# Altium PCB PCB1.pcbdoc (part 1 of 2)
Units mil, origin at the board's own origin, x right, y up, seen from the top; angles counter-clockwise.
Board outline 26305 x 7340 mil, 4 copper layers (Top Layer, Inner1, Inner2, Bottom Layer); 215 components, 225 nets, 1133 pads, 8 vias.
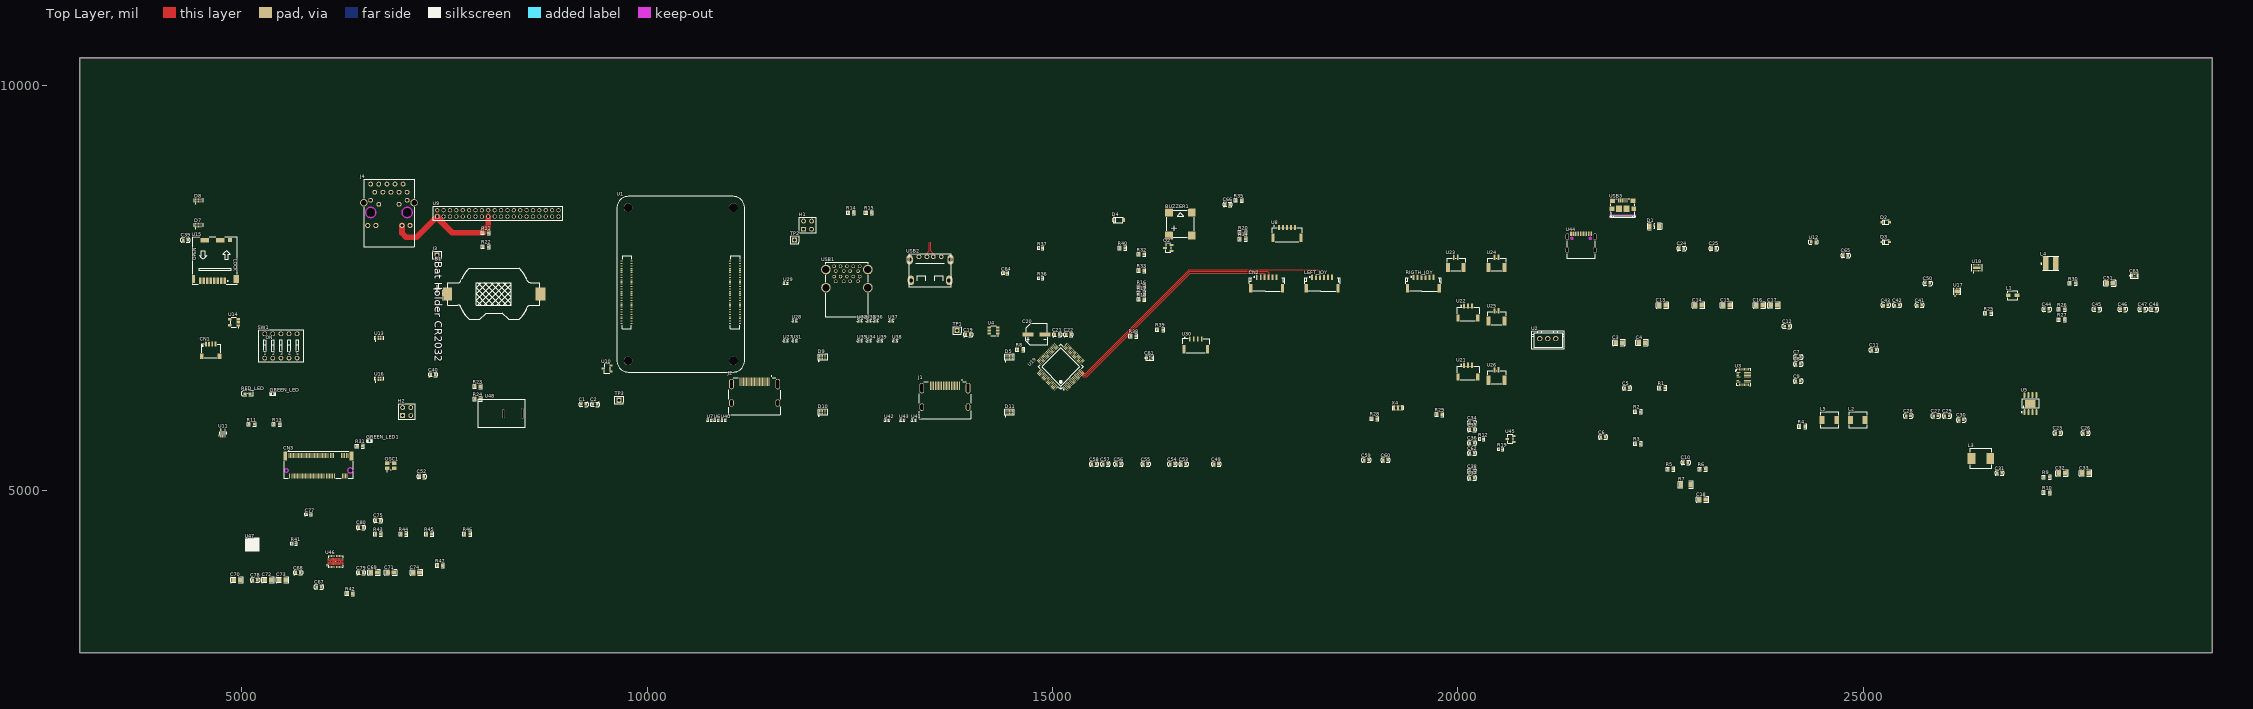
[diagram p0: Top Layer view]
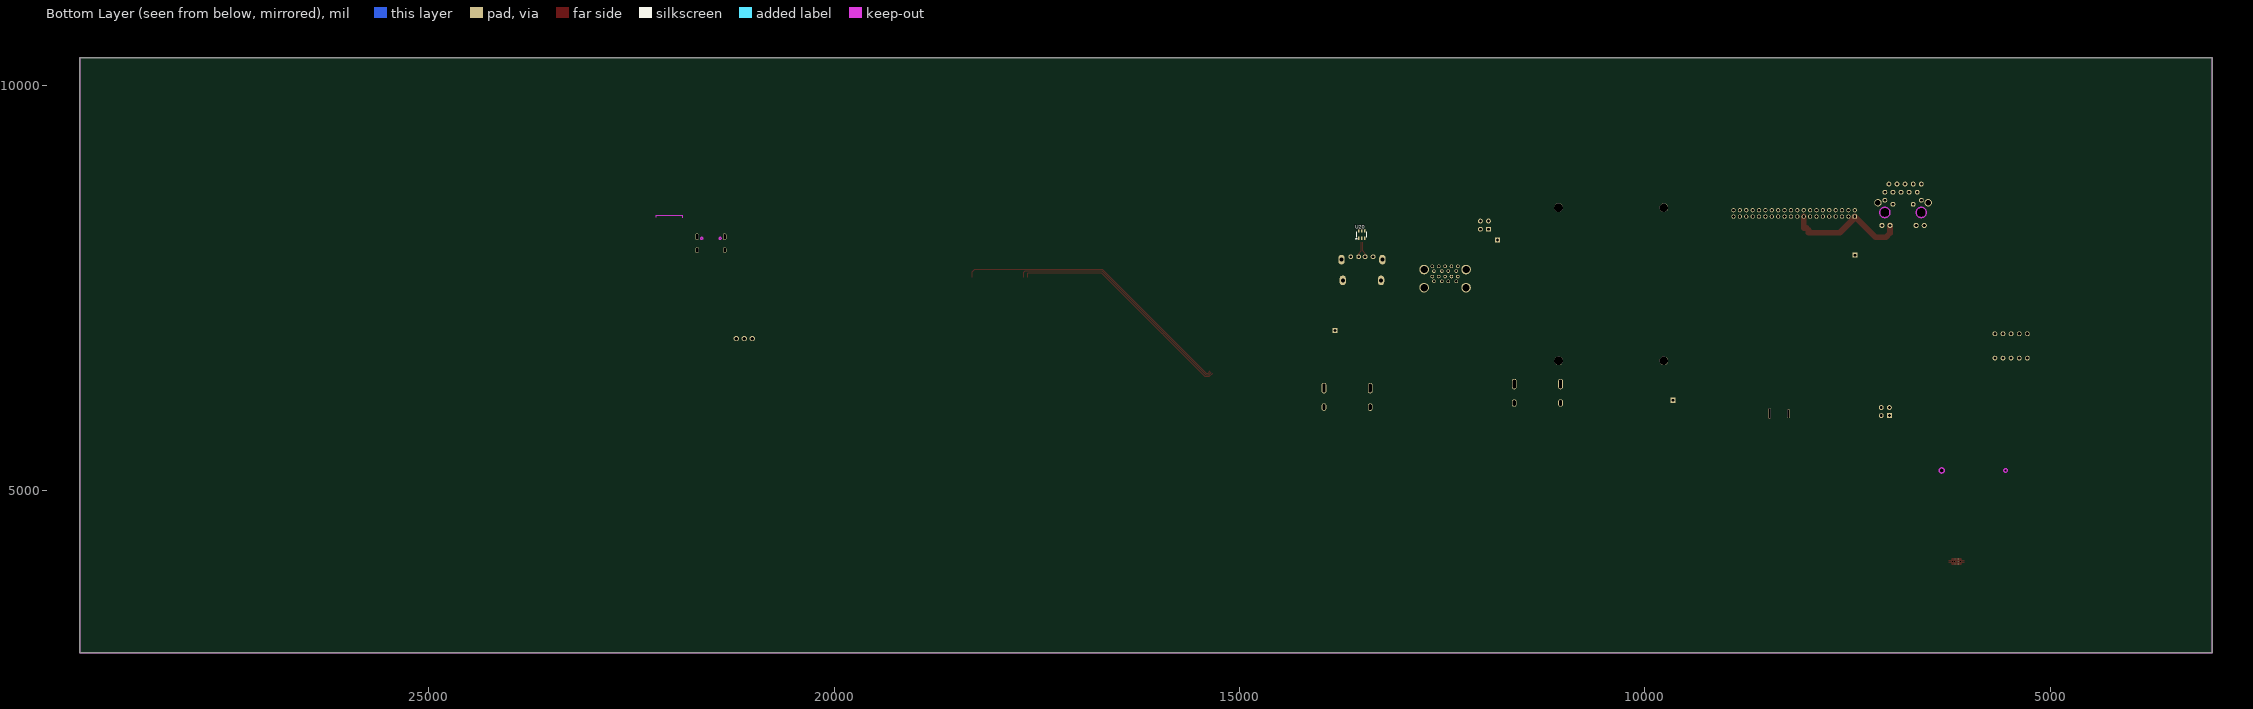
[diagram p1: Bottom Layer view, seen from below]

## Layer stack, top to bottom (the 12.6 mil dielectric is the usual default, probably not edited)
Top Layer: signal copper (thickness not stored)
Dielectric: dielectric 12.6, FR-4, Dk 4.8
Inner1: signal copper (thickness not stored)
Dielectric: dielectric 12.6, FR-4, Dk 4.8
Inner2: signal copper (thickness not stored)
Dielectric: dielectric 12.6, FR-4, Dk 4.8
Bottom Layer: signal copper (thickness not stored)

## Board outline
3000,10340 29305,10340 29305,3000 3000,3000

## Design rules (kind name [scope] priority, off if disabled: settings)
BoardOutlineClearance copperThickness1oz [All] p0: genericclearance=10 ignorepadtopadclearanceinfootprint=FALSE except(0: Arc-SplitContinuation Track-SplitContinuation SMDPad-SplitContinuation THPad-SplitContinuation Via-SplitContinuation Fill-SplitContinuation Poly-SplitContinuation Region-SplitContinuation Text-SplitContinuation; 6: Track-CutoutEdge SMDPad-CutoutEdge THPad-CutoutEdge Via-CutoutEdge Region-CutoutEdge; 11.8: Track-OutlineEdge SMDPad-OutlineEdge THPad-OutlineEdge Via-OutlineEdge Fill-OutlineEdge Region-OutlineEdge Poly-OutlineEdge Text-OutlineEdge Fill-CutoutEdge)
BoardOutlineClearance copperThickness2oz [All] p0: genericclearance=10 ignorepadtopadclearanceinfootprint=FALSE except(0: Arc-SplitContinuation Track-SplitContinuation SMDPad-SplitContinuation THPad-SplitContinuation Via-SplitContinuation Fill-SplitContinuation Poly-SplitContinuation Region-SplitContinuation Text-SplitContinuation; 6: Track-CutoutEdge SMDPad-CutoutEdge THPad-CutoutEdge Via-CutoutEdge Region-CutoutEdge; 11.8: Track-OutlineEdge SMDPad-OutlineEdge THPad-OutlineEdge Via-OutlineEdge Fill-OutlineEdge Region-OutlineEdge Poly-OutlineEdge Text-OutlineEdge Fill-CutoutEdge)
BoardOutlineClearance safeClearance1 [All] p0: genericclearance=10 ignorepadtopadclearanceinfootprint=FALSE except(0: Arc-SplitContinuation Track-SplitContinuation SMDPad-SplitContinuation THPad-SplitContinuation Via-SplitContinuation Fill-SplitContinuation Poly-SplitContinuation Region-SplitContinuation Text-SplitContinuation; 6: Track-CutoutEdge SMDPad-CutoutEdge THPad-CutoutEdge Via-CutoutEdge Fill-CutoutEdge Region-CutoutEdge; 11.8: Track-OutlineEdge SMDPad-OutlineEdge THPad-OutlineEdge Via-OutlineEdge Fill-OutlineEdge Region-OutlineEdge Poly-OutlineEdge Text-OutlineEdge)
Clearance copperThickness1oz [(InNet('AGND') OR InNet('VBAT') OR InNet('MCU_3V3') OR InNet('$4N108') OR InNet('CM_5V') OR InNet('HDMI_5V') OR InNet('$2N10') OR InNet('$2N12') OR InNet('BST1') OR InNet('SW1') OR InNet('BST2') OR InNet('SW2') OR InNet('BST3') OR InNet('SW3') OR InNet('$2N31') OR InNet('$2N30') OR InNet('IN') OR InNet('$2N37') OR InNet('SYS') OR InNet('VBUS') OR InNet('5V_USB3.0') OR InNet('$2N83') OR InNet('$2N84') OR InNet('$2N89') OR InNet('$2N91') OR InNet('+5V_RT') OR InNet('FB1') OR InNet('ADC1_IN0') OR InNet('ADC1_IN1') OR InNet('ADC1_IN2') OR InNet('ADC1_IN5') OR InNet('ADC1_IN4') OR InNet('SD_PWR') OR InNet('$3N153') OR InNet('M2_3V3') OR InNet('FB') OR InNet('$2N54') OR InNet('$2N58') OR InNet('$4N13') OR InNet('$4N14') OR InNet('SWD_5V') OR InNet('$4N18') OR InNet('ADC1_IN3') OR InNet('PWRB_STM32') OR InNet('TACHO') OR InNet('PWM') OR InNet('$3N203') OR InNet('PCIE_CLK_P') OR InNet('PCIE_NWAKE') OR InNet('PCIE_CLK_N') OR InNet('PCIE_NCLKREQ') OR InNet('PCIE_NRST') OR InNet('PCIE_TX_N') OR InNet('PCIE_TX_P') OR InNet('PCIE_RX_N') OR InNet('PCIE_RX_P') OR InNet('$3N198') OR InNet('$2N45') OR InNet('HDMI0_D2_P') OR InNet('HDMI0_D2_N') OR InNet('HDMI0_D1_P') OR InNet('HDMI0_D1_N') OR InNet('SD_DAT1') OR InNet('SD_DAT0') OR InNet('SD_CLK') OR InNet('SD_CMD') OR InNet('SD_DAT3') OR InNet('SD_DAT2') OR InNet('HDMI1_D2_P') OR InNet('HDMI1_D2_N') OR InNet('HDMI1_D1_P') OR InNet('HDMI1_D1_N') OR InNet('HDMI1_D0_P') OR InNet('HDMI1_D0_N') OR InNet('HDMI1_CK_P') OR InNet('HDMI1_CK_N') OR InNet('HDMI0_D0_P') OR InNet('HDMI0_D0_N') OR InNet('HDMI0_CK_P') OR InNet('HDMI0_CK_N') OR InNet('+3.3V') OR InNet('$3N118') OR InNet('$3N199') OR InNet('ID_SC') OR InNet('SCL1') OR InNet('ID_SD') OR InNet('SDA1') OR InNet('TR1_TAP') OR InNet('TR2_TAP') OR InNet('TR0_TAP') OR InNet('TR3_TAP') OR InNet('HDMI0_HOTPLUG') OR InNet('HDMI0_SDA') OR InNet('HDMI0_SCL') OR InNet('$1N18') OR InNet('HDMI0_CEC') OR InNet('HDMI1_HOTPLUG') OR InNet('HDMI1_SDA') OR InNet('HDMI1_SCL') OR InNet('$1N31') OR InNet('HDMI1_CEC') OR InNet('$3N62') OR InNet('$3N162') OR InNet('$3N161') OR InNet('TRD0_N') OR InNet('TRD2_N') OR InNet('TRD1_N') OR InNet('TRD3_N') OR InNet('TRD3_P') OR InNet('TRD2_P') OR InNet('TRD1_P') OR InNet('TRD0_P') OR InNet('$2N68') OR InNet('$2N57') OR InNet('$4N103') OR InNet('$2N9') OR InNet('NTC') OR InNet('$2N29') OR InNet('$1N121') OR InNet('$3N114') OR InNet('$3N115') OR InNet('$4N99') OR InNet('OFF/ON_CM5') OR InNet('LED_NACT') OR InNet('GPIO_VREF') OR InNet('ACOK') OR InNet('PROCHOT') OR InNet('INT') OR InNet('$4N114') OR InNet('LED_RED') OR InNet('+1.8V') OR InNet('ETH_LEDY') OR InNet('ETH_LEDG') OR InNet('PCIE_PWR_EN') OR InNet('$4N9') OR InNet('$4N11') OR InNet('$2N59') OR InNet('I2C1_SDA') OR InNet('I2C1_SCL') OR InNet('$4N115') OR InNet('LED_GREEN') OR InNet('$1N155') OR InNet('USB2_N') OR InNet('USB2_P') OR InNet('$1N156') OR InNet('SWDIO') OR InNet('SWCLK') OR InNet('TIM3_CH4') OR InNet('NRPIBOOT') OR InNet('EEPROM_NWP') OR InNet('USBOTG_ID') OR InNet('WIFI_NDISABLE') OR InNet('BT_NDISABLE') OR InNet('$3N7') OR InNet('GPIO26') OR InNet('CM5_GPIO_IN') OR InNet('GPIO19') OR InNet('GPIO20') OR InNet('GPIO13') OR InNet('GPIO16') OR InNet('GPIO6') OR InNet('GPIO12') OR InNet('GPIO5') OR InNet('GPIO7') OR InNet('GPIO11') OR InNet('GPIO8') OR InNet('GPIO9') OR InNet('GPIO25') OR InNet('GPIO10') OR InNet('GPIO24') OR InNet('GPIO22') OR InNet('GPIO23') OR InNet('GPIO27') OR InNet('GPIO18') OR InNet('GPIO17') OR InNet('GPIO15') OR InNet('GPIO4') OR InNet('GPIO14') OR InNet('GPIO3') OR InNet('GPIO2') OR InNet('$3N25') OR InNet('SD_PWR_ON') OR InNet('PWR_BUT') OR InNet('CC1') OR InNet('NPWR_LED') OR InNet('CC2') OR InNet('$1N122') OR InNet('VBUS_EN') OR InNet('USB3-0-RX_N') OR InNet('USB3-0-RX_P') OR InNet('USB3-0-D_P') OR InNet('USB3-0-D_N') OR InNet('$1N88') OR InNet('USB3-0-TX_N') OR InNet('$1N87') OR InNet('USB3-0-TX_P') OR InNet('USB3-1-RX_N') OR InNet('USB3-1-RX_P') OR InNet('USB3-1-D_P') OR InNet('USB3-1-D_N') OR InNet('USB3-1-TX_N') OR InNet('USB3-1-TX_P') OR InNet('EN_5V') OR InNet('GPIO_IN1') OR InNet('GPIO_IN0') OR InNet('GPIO_IN7') OR InNet('GPIO_IN6') OR InNet('GPIO_IN5') OR InNet('GPIO_IN4') OR InNet('GPIO_IN3') OR InNet('GPIO_IN2') OR InNet('$4N8') OR InNet('$4N7') OR InNet('D+') OR InNet('D-') OR InNet('$2N3270') OR InNet('$2N3397') OR InNet('$2N3401') OR InNet('$2N4875') OR InNet('$2N4576') OR InNet('$2N4443') OR InNet('$2N4479') OR InNet('$2N3574') OR InNet('$2N3583') OR InNet('$2N4890'))] p1: gap=7 ignorepadtopadclearanceinfootprint=FALSE except(4: Track-Track; 6: Track-SMDPad SMDPad-SMDPad Track-THPad SMDPad-THPad THPad-THPad Track-Via SMDPad-Via THPad-Via Via-Via SMDPad-Fill THPad-Fill Via-Fill Fill-Fill Track-Region SMDPad-Region THPad-Region Via-Region Region-Region Track-Poly SMDPad-Poly THPad-Poly Via-Poly Fill-Poly Region-Poly Poly-Poly Track-Text SMDPad-Text THPad-Text Via-Text Fill-Text Region-Text Poly-Text Text-Text; 6.9: Track-Hole SMDPad-Hole THPad-Hole Via-Hole Fill-Hole Region-Hole Poly-Hole Text-Hole Sheet-Hole; 11.8: Track-Fill Fill-Region Track-Sheet SMDPad-Sheet THPad-Sheet Via-Sheet Fill-Sheet Region-Sheet Poly-Sheet Text-Sheet)
Clearance copperThickness2oz [All] p1: gap=7 ignorepadtopadclearanceinfootprint=FALSE except(6: Track-SMDPad SMDPad-SMDPad Track-THPad SMDPad-THPad THPad-THPad Track-Via SMDPad-Via THPad-Via Via-Via SMDPad-Fill THPad-Fill Via-Fill Fill-Fill Track-Region SMDPad-Region THPad-Region Via-Region Region-Region Track-Poly SMDPad-Poly THPad-Poly Via-Poly Fill-Poly Region-Poly Poly-Poly Track-Text SMDPad-Text THPad-Text Via-Text Fill-Text Region-Text Poly-Text Text-Text; 6.9: Track-Hole SMDPad-Hole THPad-Hole Via-Hole Fill-Hole Region-Hole Poly-Hole Text-Hole Sheet-Hole; 8: Track-Track; 11.8: Track-Fill Fill-Region Track-Sheet SMDPad-Sheet THPad-Sheet Via-Sheet Fill-Sheet Region-Sheet Poly-Sheet Text-Sheet)
Clearance safeClearance1 [All] p1: gap=7 ignorepadtopadclearanceinfootprint=FALSE except(6: Track-Track Track-SMDPad SMDPad-SMDPad Track-THPad SMDPad-THPad THPad-THPad Track-Via SMDPad-Via THPad-Via Via-Via Track-Fill SMDPad-Fill THPad-Fill Via-Fill Fill-Fill Track-Region SMDPad-Region THPad-Region Via-Region Fill-Region Region-Region Track-Poly SMDPad-Poly THPad-Poly Via-Poly Fill-Poly Region-Poly Poly-Poly Track-Text SMDPad-Text THPad-Text Via-Text Fill-Text Region-Text Poly-Text Text-Text Track-Hole SMDPad-Hole THPad-Hole Via-Hole Fill-Hole Region-Hole Poly-Hole Text-Hole; 11.8: Track-Sheet SMDPad-Sheet THPad-Sheet Via-Sheet Fill-Sheet Region-Sheet Poly-Sheet Text-Sheet Sheet-Hole)
DiffPairsRouting differentialPair [All] p1: maxuncoupledlength=10 minlimit=6 maxlimit=6 mostfreqgap=6 toplayer_minwidth=5 toplayer_prefwidth=10 toplayer_maxwidth=100 bottomlayer_minwidth=5 bottomlayer_prefwidth=10 bottomlayer_maxwidth=100 midlayer1_minwidth=5 midlayer1_prefwidth=10 midlayer1_maxwidth=100 midlayer2_minwidth=5 midlayer2_prefwidth=10 midlayer2_maxwidth=100
PasteMaskExpansion pasteMaskExpansion [All] p1: expansion=0
PlaneConnect innerPlane [All] p1: planeconnectstyle=Relief reliefexpansion=20 reliefentries=4 reliefconductorwidth=10 reliefairgap=10
PolygonConnect copperRegion [All] p1: connectstyle=Relief reliefentries=4 reliefconductorwidth=10 polygonreliefangle="90 Angle" airgapwidth=10
RoutingVias viaSize [All] p1: viastyle="Through Hole" holewidth=12.0078 minholewidth=11.811 maxholewidth=248.0314 width=24.0158 minwidth=19.685 maxwidth=393.7008
SolderMaskExpansion solderMaskExpansion [All] p1: useseparateexpansions=TRUE expansion=2 expansionbottom=2
Width copperThickness1oz [All] p1: maxlimit=100 minlimit=5 preferedwidth=10
Width copperThickness2oz [All] p1: maxlimit=100 minlimit=8 preferedwidth=10
Width Power [All] p1: maxlimit=197 minlimit=59 preferedwidth=71

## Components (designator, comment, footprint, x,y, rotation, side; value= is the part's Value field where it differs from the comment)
B1 "KLS5-CR1220-01" L-KLS5-CR2032-23-B1 8108.44,7425.03 r0 top
BUZZER1 "2700Hz" BUZ-SMD_4P-L8.5-W8.5-P8.50-BR 16576.98,8287.53 r0 top
C1 "100nF" C0603 9216.73,6064.16 r0 top
C2 "100nF" C0603 9355.86,6064.16 r0 top
C3 "22uF" C0805 21984.28,6824.69 r0 top
C4 "22uF" C0805 22271.22,6824.69 r0 top
C5 "100nF" C0603 22084.28,6263.8 r0 top
C6 "1uF" C0603 21788.46,5659.49 r0 top
C7 "470nF" C0603 24196.57,6647.87 r0 top
C8 "470nF" C0603 24196.57,6562.28 r0 top
C9 "470nF" C0603 24196.57,6349.4 r0 top
C10 "100nF" C0603 22808.16,5346.2 r0 top
C11 "1uF" C0603 25130.65,6733.47 r0 top
C12 "10uF" C0603 24057.44,7026.81 r0 top
C13 "22uF" C0805 22521.22,7286.16 r0 top
C14 "22uF" C0805 22967.88,7286.16 r0 top
C15 "22uF" C0805 23314.53,7286.16 r0 top
C16 "22uF" C0805 23717.43,7286.16 r0 top
C17 "22uF" C0805 23897.73,7286.16 r0 top
C18 "22uF" C0805 23017.88,4888.93 r0 top
C19 "10uF" C0603 13958.15,6923.07 r0 top
C20 "100uF" CAP-SMD_BD6.3-L6.6-W6.6-LS7.6-FD 14802.8,6923.07 r0 top
C21 "10uF" C0603 15056.22,6923.07 r0 top
C22 "10uF" C0603 15195.35,6923.07 r0 top
C23 "3.3nF" C0603 27398.31,5709.49 r0 top
C24 "100nF" C0603 22758.16,7985.11 r0 top
C25 "100nF" C0603 23154.81,7985.11 r0 top
C26 "1uF" C0603 27740.58,5709.49 r0 top
C27 "10uF" C0603 25893.31,5922.79 r0 top
C28 "10uF" C0603 25554.18,5922.79 r0 top
C29 "100nF" C0603 26032.44,5922.79 r0 top
C30 "100nF" C0603 26207.22,5872.79 r0 top
C31 "5pF" C0603 26678.62,5214.55 r0 top
C32 "22uF" C0805 27448.31,5214.55 r0 top
C33 "22uF" C0805 27740.58,5214.55 r0 top
C34 "100nF" C0603 20173.12,5837.26 r0 top
C35 "100nF" C0603 20173.12,5751.66 r0 top
C36 "100nF" C0603 20173.12,5586.52 r0 top
C37 "100nF" C0603 20173.12,5154.47 r0 top
C38 "100nF" C0603 20173.12,5240.06 r0 top
C39 "10uF" C0603 4304.72,8090.01 r0 top
C40 "0.1u" C0603 7358.44,6430.65 r0 top
C41 "100nF" C0603 25693.31,7286.16 r0 top
C42 "10uF" C0603 25415.05,7286.16 r0 top
C43 "10uF" C0603 25275.91,7286.16 r0 top
C44 "4.7nF" C0603 27261.37,7236.16 r0 top
C45 "10uF" C0603 27879.71,7236.16 r0 top
C46 "10uF" C0603 28199.14,7236.16 r0 top
C47 "10uF" C0603 28444.49,7236.16 r0 top
C48 "10uF" C0603 28583.62,7236.16 r0 top
C49 "1uF" C0603 17019.02,5325.66 r0 top
C50 "2.2uF" C0603 25793.31,7556.38 r0 top
C51 "22uF" C0805 28039.43,7556.38 r0 top
C52 "100nF" C0603 7219.31,5174.46 r0 top
C53 "100nF" C0603 16616.11,5325.66 r0 top
C54 "100nF" C0603 16476.98,5325.66 r0 top
C55 "100nF" C0603 16147.22,5325.66 r0 top
C56 "100nF" C0603 15812.47,5325.66 r0 top
C57 "100nF" C0603 15650.78,5325.66 r0 top
C58 "100nF" C0603 15511.64,5325.66 r0 top
C59 "2.2uF" C0603 18869.94,5375.66 r0 top
C60 "2.2uF" C0603 19106.88,5375.66 r0 top
C61 "-" FILTER-SMD_3P-L1.6-W0.8-L_NFM18CC223R1C3D 16197.22,6635.93 r0 top
C62 "100nF" C0603 20173.12,5461.26 r0 top
C63 "-" FILTER-SMD_3P-L1.6-W0.8-L_NFM18CC223R1C3D 28344.49,7649.51 r0 top
C64 "100nF" C0402 14416.65,7683.96 r0 top
C65 "47uF" C0603 24781.17,7899.51 r0 top
C66 "100nF" C0603 17158.15,8529.14 r0 top
C67 "06035C473KAT2A" C0603 5951.14,3811.55 r0 top
C68 "CC0603KRX7R9BB104" C0603 5694.3,3988.36 r0 top
C69 "GRM219R61C226ME15L" C0805 6630.13,3988.36 r0 top
C70 "GRM219R61C226ME15L" C0805 4939.12,3897.15 r0 top
C71 "GRM219R61C226ME15L" C0805 6837.65,3988.36 r0 top
C72 "GRM219R61C226ME15L" C0805 5323.83,3897.15 r0 top
C73 "GRM219R61C226ME15L" C0805 5504.13,3897.15 r0 top
C74 "GRM219R61C226ME15L" C0805 7152.7,3988.36 r0 top
C75 "CC0603KRX7R9BB102" C0603 6680.13,4631.33 r0 top
C77 "GRM155R61C225KE11D" C0402 5822.72,4706.6 r0 top
C78 "CC0603KRX7R9BB104" C0603 5164.12,3897.15 r0 top
C79 "CC0603KRX7R9BB104" C0603 6470.41,3988.36 r0 top
C80 "CAP_0603" C0603 6470.41,4545.73 r0 top
CN1 "SM04B-SRSS-TB (LF)(SN)" CONN-SMD_4P-P1.00_SM04B-SRSS-TB-LF-SN 4616.59,6733.4 r0 top
CN2 "STICK LEFT" CONN-TH_SM06B-GHS-TB-LF-SN 17641.21,7563.61 r0 top
CN3 "MDT275M02001-CUST" PCI-SMD_APCI0164-P001A 5944.79,5307.1 r0 top
D1 "MF-NSML600/6-2" F1206 22421.22,8261.12 r0 top
D2 "BAT60AE6327HTSA1" SOD-323_L1.8-W1.3-LS2.5-RD 25275.91,8311.12 r0 top
D3 "BAT60AE6327HTSA1" SOD-323_L1.8-W1.3-LS2.5-RD 25275.91,8066.39 r0 top
D4 "BAS16W" SOD-123_L2.7-W1.6-LS3.7-RD 15812.47,8337.53 r0 top
D5 "ESD73034D" DFN-10_L2.5-W1.0-P0.50-BL-2 14466.65,6645.85 r0 top
D7 "TPD4E02B04DQAR" USON-10_L2.5-W1.0-P0.50-BL 4466.59,8275.39 r0 top
D8 "TPD4E02B04DQAR" USON-10_L2.5-W1.0-P0.50-BL 4466.59,8579.84 r0 top
D9 "ESD73034D" DFN-10_L2.5-W1.0-P0.50-BL-2 12163.41,6645.85 r0 top
D10 "ESD73034D" DFN-10_L2.5-W1.0-P0.50-BL-2 12163.41,5967.59 r0 top
D11 "ESD73034D" DFN-10_L2.5-W1.0-P0.50-BL-2 14466.65,5967.59 r0 top
GREEN_LED "TO-1608BC" 1608 5382.57,6196.27 r0 top
GREEN_LED1 "TO-1608BC" 1608 6574.72,5614.73 r0 top
H1 "HDR-F-2.54_2x2" HDR-F-2.54_2X2 11978.78,8273.54 r0 top
H2 "HDR-F-2.54_2x2" HDR-F-2.54_2X2 7033.9,5973.82 r0 top
J1 "CM4IO_HDMI_A_1.4" "EDAC 690-019-298-412" 13672.29,6264.16 r0 top
J2 "CM4IO_HDMI_A_1.4" "EDAC 690-019-298-412" 11325.09,6314.16 r0 top
J3 "3.3V_eMMC" HDR-M-2.54_1X1 7408.44,7903.21 r0 top
J4 "LPJG0926HENL" RJ45-TH_LPJG0926HENL_C22457393 6815,8525 r0 top
L1 "2.2uH" IND-SMD_L3.0-W3.0_IHLP-1212BZ 26840.7,7408.48 r0 top
L2 "1.5uH" IND-SMD_L5.5-W5.2 24931.17,5872.79 r0 top
L3 "3.3uH" IND-SMD_L6.5-W6.5_IHLP-2525 26449.41,5396.2 r0 top
L4 "10uH" IND-SMD_L4.0-W4.0_VLCF4020 27311.37,7799.51 r0 top
L5 "1.5uH" IND-SMD_L5.5-W5.2 24581.69,5872.79 r0 top
LEFT_JOY "STICK RIGHT" CONN-TH_SM06B-GHS-TB-LF-SN 18324.8,7563.61 r0 top
OSC1 "32.768kHz" OSC-SMD_4P-L3.2-W2.5-BL-1 6835.89,5307.1 r0 top
Q2 "SS8050" SOT-23-3_L2.9-W1.3-P1.90-LS2.4-BR 16426.98,7992.34 r0 top
R1 "100Ω" R0603 22521.22,6263.8 r0 top
R2 "13.7kΩ" R0603 22221.22,5972.79 r0 top
R3 "37.4kΩ" R0603 22221.22,5577.84 r0 top
R4 "10k" R0603 24246.57,5791.14 r0 top
R5 "2Ω" R0603 22621.22,5264.55 r0 top
R6 "2Ω" R0603 23017.88,5264.55 r0 top
R7 "10mΩ" R1206 22808.16,5070.37 r0 top
R8 "15kΩ" R0603 14602.8,6738.48 r0 top
R9 "124k" R0603 27261.37,5164.55 r0 top
R10 "22.1k" R0603 27261.37,4976.2 r0 top
R11 "1k" R0603 5121.66,5817.67 r0 top
R12 "100Ω" R0402 20292.71,5636.52 r0 top
R13 "1k" R0603 5432.57,5817.67 r0 top
R14 "2.2k 1%" R0603 12513.41,8428.23 r0 top
R15 "2.2k 1%" R0603 12734.83,8428.23 r0 top
R16 "10k" R0603 16097.22,7513.61 r0 top
R17 "10k" R0603 16097.22,7435.91 r0 top
R18 "10k" R0603 16097.22,7358.21 r0 top
R19 "100kOm" R0402 20525.6,5511.26 r0 top
R20 "300" R0603 17345.09,8181.82 r0 top
R21 "0" R0603 8008.44,8178.7 r0 top
R22 "0" R0603 8008.44,8008.36 r0 top
R23 "470" R0603 7908.44,6283.96 r0 top
R24 "470" R0603 7908.44,6128.51 r0 top
R25 "100k" R0603 26541.68,7186.16 r0 top
R26 "10k" R0603 27448.31,7236.16 r0 top
R27 "2.2k" R0603 27448.31,7108.46 r0 top
R28 "10k" R0603 18969.94,5887.26 r0 top
R29 "10k" R0603 19772.88,5937.26 r0 top
R30 "100k" R0603 27583.05,7556.38 r0 top
R31 "1k" R0603 6457.01,5546.98 r0 top
R32 "10k" R0603 16097.22,7914.64 r0 top
R33 "10k" R0603 16097.22,7714.64 r0 top
R34 "300" R0603 17345.09,8104.12 r0 top
R35 "10k" R0603 17295.09,8579.14 r0 top
R36 "22Ω" R0402 14852.8,7619.01 r0 top
R37 "22Ω" R0402 14852.8,7992.62 r0 top
R38 "10k" R0603 15997.22,6906.58 r0 top
R39 "10k" R0603 16326.98,6984.28 r0 top
R40 "1k" R0603 15862.47,7992.34 r0 top
R41 "RC0402FR-07590KL" R0402 5644.3,4346.29 r0 top
R42 "RC0603FR-07100KL" R0603 6333.47,3729.91 r0 top
R43 "Res_0603" R0603 6680.13,4464.09 r0 top
R44 "RC0603FR-07100KL" R0603 6995.17,4464.09 r0 top
R45 "RC0603FR-0795K3L" R0603 7310.22,4464.09 r0 top
R46 "RC0603FR-07127KL" R0603 7781.24,4464.09 r0 top
R47 "RC0603FR-07316KL" R0603 7444.97,4075.63 r0 top
RED_LED "TO-1608BC" SENSOR-SMD_L1.6-W0.8-XL-1608PDC 5071.66,6196.27 r0 top
RIGTH_JOY "STICK CAMERA GIMBAL" CONN-TH_SM06B-GHS-TB-LF-SN 19572.88,7563.61 r0 top
SW1 "DS1040-05RT" SW-TH_10P-P2.54_DS1040-05RN 5482.57,6783.4 r0 top
TP1 "HDR-M-2.54_1x1" HDR-M-2.54_1X1 13822.29,6973.07 r0 top
TP2 "HDR-M-2.54_1x1" HDR-M-2.54_1X1 11818.14,8089.93 r0 top
TP3 "HDR-M-2.54_1x1" HDR-M-2.54_1X1 9652.52,6114.16 r0 top
U1 "Raspberry Pi CM5" CM5IO:Raspberry-Pi-5-Compute-Module 9765,6600 r0 top
U2 "BAT 2s" CONN-TH_XH2.54-3P 21107.78,6874.69 r0 top
U3 "MP2762AGV-0000-Z" QFN-30_L5.0-W4.0-P0.50-TL_MP2762A 23517.04,6399.4 r0 top
U4 "AP22653W6-7" SOT-23-6_L2.9-W1.6-P0.95-LS2.8-BR 14273.15,6973.07 r0 top
U5 "RT6206BHGSP" SOP-8_L4.9-W3.9-P1.27-LS6.0-BL-EP-2 27060.09,6072.79 r0 top
U6 "ESD5311N" DFN1006-2L-BI 10855.5,5871.1 r0 top
U7 "ESD5311N" DFN1006-2L-BI 10768.83,5871.1 r0 top
U8 "Power_button" CONN-SMD_5P-P1.25_SM05B-GHS-TB-LF-SN 17891.21,8181.82 r0 top
U9 "DS1023-2X20" HDR-TH_40P-P2.00-V-F-R2-C20-S2.00 8158.44,8418.64 r0 top
U10 "RT9742SNGV_C3235509" SOT-23-3_L2.9-W1.6-P1.90-LS2.8-BR 9504.96,6503.63 r0 top
U11 "74LVC1G07SE-7" SC-88A_L2.0-W1.3-P0.65-LS2.1-BL 4766.59,5711.22 r0 top
U12 "BLM18PG121SH1D" L0603 24382.86,8066.39 r0 top
U13 "TPD4EUSB30DQAR" USON-10_L2.5-W1.0-P0.50-BL 6690.12,6883.4 r0 top
U14 "RT9742GGJ5" TSOT-23-5_L2.9-W1.6-P0.95-LS2.8-BR 4902.87,7075.03 r0 top
U15 "SD CARD SOCKET DM3C-SF HIROSE" TF-SMD_DM3CS-SF 4666.59,7840.01 r0 top
U16 "TPD4EUSB30DQAR" USON-10_L2.5-W1.0-P0.50-BL 6690.12,6380.65 r0 top
U17 "AP3441SHE-7B" DFN2020-8_L2.0-W2.0-P0.50-BL-EP 26157.22,7458.48 r0 top
U18 "TPS62177DQCR" WSON-10_L3.0-W2.0-P0.50-BL-EP 26399.41,7749.51 r0 top
U19 "STM32F405RGT6" LQFP-64_L10.0-W10.0-P0.50-LS12.0-BL 15100.43,6525.23 r45 top
U20 "USBLC6-2SC6_C6807798" SOT-23-6_L2.9-W1.6-P0.95-LS2.8-BL 13491.61,8156.83 r180 bottom
U21 "3 pos" CONN-TH_SM03B-GHS-TB-LF-SN 20123.12,6474.92 r0 top
U22 "3 pos" CONN-TH_SM03B-GHS-TB-LF-SN 20123.12,7203.05 r0 top
U23 "2 pos" CONN-SMD_SM02B-GHS-TB-LF-SN 19973.12,7814.64 r0 top
U24 "2 pos" CONN-SMD_SM02B-GHS-TB-LF-SN 20475.6,7814.64 r0 top
U25 "2 pos" CONN-SMD_SM02B-GHS-TB-LF-SN 20475.6,7153.05 r0 top
U26 "2 pos" CONN-SMD_SM02B-GHS-TB-LF-SN 20475.6,6424.92 r0 top
U27 "ESD5311N" DFN1006-2L-BI 11709.96,6852.69 r0 top
U28 "ESD5311N" DFN1006-2L-BI 11818.14,7096.43 r0 top
U29 "ESD5311N" DFN1006-2L-BI 11709.96,7558.95 r0 top
U30 "SM04B-GHS-TB(LF)(SN)" CONN-SMD_4P-P1.25_SM04B-GHS-TB-LF-SN 16766.11,6806.58 r0 top
U31 "ESD5311N" DFN1006-2L-BI 11818.14,6852.69 r0 top
U32 "ESD5311N" DFN1006-2L-BI 12624.12,7096.43 r0 top
U33 "ESD5311N" DFN1006-2L-BI 12734.83,7096.43 r0 top
U34 "ESD5311N" DFN1006-2L-BI 12734.83,6852.69 r0 top
U35 "ESD5311N" DFN1006-2L-BI 12624.12,6852.69 r0 top
U36 "ESD5311N" DFN1006-2L-BI 12821.51,7096.43 r0 top
U37 "ESD5311N" DFN1006-2L-BI 13008.18,7096.43 r0 top
U38 "ESD5311N" DFN1006-2L-BI 13058.18,6852.69 r0 top
U39 "ESD5311N" DFN1006-2L-BI 12871.51,6852.69 r0 top
U40 "ESD5311N" DFN1006-2L-BI 10942.18,5871.1 r0 top
U41 "ESD5311N" DFN1006-2L-BI 13289.38,5871.1 r0 top
U42 "ESD5311N" DFN1006-2L-BI 12958.18,5871.1 r0 top
U43 "ESD5311N" DFN1006-2L-BI 13144.86,5871.1 r0 top
U44 "TYPE-C" USB-C-SMD_TYPE-C16PIN-SHOUHAN 21519.18,8066.39 r0 top
U45 "BSS138" SOT-23-3_L2.9-W1.4-P1.90-LS2.5-BR 20647.27,5636.52 r0 top
U46 "TPS61088RHLR" VQFN-20_L4.6-W3.6-P0.50-BL 6156.46,4125.63 r0 top
U47 "CDCSAB0420-1R5M" CDCSAB0420-1R5M 5664.12,4046.29 r0 top
U48 "DS-201" DS-201 7919.61,6126.85 r0 top
USB1 "HC-USB3.0-L175-2X1-P" USB-A-TH_H181-AF2R06-12ALCR 12463.41,7633.96 r0 top
USB2 "USB-A DS1095-06-BNR0" DS1095-06-BNR0 13489.38,7883.96 r0 top
USB3 "1981568-1" MICRO-USB-SMD_1981568-1 22034.28,8528.92 r0 top
X4 "8MHz" OSC-SMD_3P-L3.2-W1.3-P1.2-L 19260.29,6019.42 r0 top

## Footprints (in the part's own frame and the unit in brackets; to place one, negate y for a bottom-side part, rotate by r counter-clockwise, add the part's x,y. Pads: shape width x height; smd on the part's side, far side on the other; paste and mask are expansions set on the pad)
1608 [mil]
  rect 26x38 smd: 1(-27.5,0) 2(27.5,0)
  silkscreen extent -34,-19 34,19
BUZ-SMD_4P-L8.5-W8.5-P8.50-BR [mil]
  rect 94.49x94.49 smd: 1(-141.72,-141.73) 2(141.72,-141.73) 3(141.72,141.72) 4(-141.72,141.73)
  silkscreen extent -167,-167 167,167
C0402 [mm]
  rect 0.79x0.54 smd: 1(-0.545,0) 2(0.545,0)
  silkscreen extent -1.17,-0.5 1.17,0.5
C0603 [mm]
  rect 0.8x0.9 smd: 1(-0.7,0) 2(0.7,0)
  silkscreen extent -1.39,-0.71 1.39,0.71
C0805 [mm]
  rect 1.41x1.35 smd: 1(-1,0) 2(1,0)
  silkscreen extent -1.96,-0.9 1.96,0.9
CAP-SMD_BD6.3-L6.6-W6.6-LS7.6-FD [mm]
  rect 3.5x1.2 smd: 1(-2.67,0) 2(2.67,0)
  silkscreen extent -3.38,-3.38 3.38,3.38
CDCSAB0420-1R5M [mm]
  rect 0.8x2 smd: 1(-15.475,7.255) 2(-11.811,7.239)
  silkscreen extent -15.85,5.17 -11.45,9.37
CM5IO:Raspberry-Pi-5-Compute-Module [mm]
  rect 0.7x0.2 smd: 1(-2.04,31.3) 2(1.04,31.3) 3(-2.04,30.9) 4(1.04,30.9) 5(-2.04,30.5) 6(1.04,30.5) 7(-2.04,30.1) 8(1.04,30.1) 9(-2.04,29.7) 10(1.04,29.7) 11(-2.04,29.3) 12(1.04,29.3) 13(-2.04,28.9) 14(1.04,28.9) 15(-2.04,28.5) 16(1.04,28.5) 17(-2.04,28.1) 18(1.04,28.1) 19(-2.04,27.7) 20(1.04,27.7) 21(-2.04,27.3) 22(1.04,27.3) 23(-2.04,26.9) 24(1.04,26.9) 25(-2.04,26.5) 26(1.04,26.5) 27(-2.04,26.1) 28(1.04,26.1) 29(-2.04,25.7) 30(1.04,25.7) 31(-2.04,25.3) 32(1.04,25.3) 33(-2.04,24.9) 34(1.04,24.9) 35(-2.04,24.5) 36(1.04,24.5) 37(-2.04,24.1) 38(1.04,24.1) 39(-2.04,23.7) 40(1.04,23.7) 41(-2.04,23.3) 42(1.04,23.3) 43(-2.04,22.9) 44(1.04,22.9) 45(-2.04,22.5) 46(1.04,22.5) 47(-2.04,22.1) 48(1.04,22.1) 49(-2.04,21.7) 50(1.04,21.7) 51(-2.04,21.3) 52(1.04,21.3) 53(-2.04,20.9) 54(1.04,20.9) 55(-2.04,20.5) 56(1.04,20.5) 57(-2.04,20.1) 58(1.04,20.1) 59(-2.04,19.7) 60(1.04,19.7) 61(-2.04,19.3) 62(1.04,19.3) 63(-2.04,18.9) 64(1.04,18.9) 65(-2.04,18.5) 66(1.04,18.5) 67(-2.04,18.1) 68(1.04,18.1) 69(-2.04,17.7) 70(1.04,17.7) 71(-2.04,17.3) 72(1.04,17.3) 73(-2.04,16.9) 74(1.04,16.9) 75(-2.04,16.5) 76(1.04,16.5) 77(-2.04,16.1) 78(1.04,16.1) 79(-2.04,15.7) 80(1.04,15.7) 81(-2.04,15.3) 82(1.04,15.3) 83(-2.04,14.9) 84(1.04,14.9) 85(-2.04,14.5) 86(1.04,14.5) 87(-2.04,14.1) 88(1.04,14.1) 89(-2.04,13.7) 90(1.04,13.7) 91(-2.04,13.3) 92(1.04,13.3) 93(-2.04,12.9) 94(1.04,12.9) 95(-2.04,12.5) 96(1.04,12.5) 97(-2.04,12.1) 98(1.04,12.1) 99(-2.04,11.7) 100(1.04,11.7) 101(31.96,31.3) 102(35.04,31.3) 103(31.96,30.9) 104(35.04,30.9) 105(31.96,30.5) 106(35.04,30.5) 107(31.96,30.1) 108(35.04,30.1) 109(31.96,29.7) 110(35.04,29.7) 111(31.96,29.3) 112(35.04,29.3) 113(31.96,28.9) 114(35.04,28.9) 115(31.96,28.5) 116(35.04,28.5) 117(31.96,28.1) 118(35.04,28.1) 119(31.96,27.7) 120(35.04,27.7) 121(31.96,27.3) 122(35.04,27.3) 123(31.96,26.9) 124(35.04,26.9) 125(31.96,26.5) 126(35.04,26.5) 127(31.96,26.1) 128(35.04,26.1) 129(31.96,25.7) 130(35.04,25.7) 131(31.96,25.3) 132(35.04,25.3) 133(31.96,24.9) 134(35.04,24.9) 135(31.96,24.5) 136(35.04,24.5) 137(31.96,24.1) 138(35.04,24.1) 139(31.96,23.7) 140(35.04,23.7) 141(31.96,23.3) 142(35.04,23.3) 143(31.96,22.9) 144(35.04,22.9) 145(31.96,22.5) 146(35.04,22.5) 147(31.96,22.1) 148(35.04,22.1) 149(31.96,21.7) 150(35.04,21.7) 151(31.96,21.3) 152(35.04,21.3) 153(31.96,20.9) 154(35.04,20.9) 155(31.96,20.5) 156(35.04,20.5) 157(31.96,20.1) 158(35.04,20.1) 159(31.96,19.7) 160(35.04,19.7) 161(31.96,19.3) 162(35.04,19.3) 163(31.96,18.9) 164(35.04,18.9) 165(31.96,18.5) 166(35.04,18.5) 167(31.96,18.1) 168(35.04,18.1) 169(31.96,17.7) 170(35.04,17.7) 171(31.96,17.3) 172(35.04,17.3) 173(31.96,16.9) 174(35.04,16.9) 175(31.96,16.5) 176(35.04,16.5) 177(31.96,16.1) 178(35.04,16.1) 179(31.96,15.7) 180(35.04,15.7) 181(31.96,15.3) 182(35.04,15.3) 183(31.96,14.9) 184(35.04,14.9) 185(31.96,14.5) 186(35.04,14.5) 187(31.96,14.1) 188(35.04,14.1) 189(31.96,13.7) 190(35.04,13.7) 191(31.96,13.3) 192(35.04,13.3) 193(31.96,12.9) 194(35.04,12.9) 195(31.96,12.5) 196(35.04,12.5) 197(31.96,12.1) 198(35.04,12.1) 199(31.96,11.7) 200(35.04,11.7)
  round 2.7 hole 2.7 unplated: ""(0,0) ""(0,48) ""(33,0) ""(33,48)
  silkscreen extent -3.5,-3.5 36.5,51.5
CONN-SMD_4P-P1.00_SM04B-SRSS-TB-LF-SN [mm]
  rect 0.6x1.55 smd: 1(-1.5,1.938) 2(-0.5,1.938) 3(0.5,1.938) 4(1.5,1.938)
  rect 1.2x1.8 smd: 5(2.8,-1.938) 6(-2.8,-1.938)
  silkscreen extent -3.02,-2.46 2.96,1.8
CONN-SMD_4P-P1.25_SM04B-GHS-TB-LF-SN [mm]
  rect 0.6x1.7 smd: 1(-1.876,1.6) 2(-0.626,1.6) 3(0.625,1.6) 4(1.875,1.6)
  rect 1x2.7 smd: 5(3.725,-1.6) 6(-3.725,-1.6)
  silkscreen extent -4.27,-2.71 4.28,2.22
CONN-SMD_5P-P1.25_SM05B-GHS-TB-LF-SN [mm]
  rect 0.6x1.7 smd: 1(-2.5,1.6) 2(-1.25,1.6) 3(0,1.6) 4(1.25,1.6) 5(2.5,1.6)
  rect 1x2.7 smd: 6(4.35,-1.6) 7(-4.35,-1.6)
  silkscreen extent -4.83,-2.79 4.83,2.24
CONN-SMD_SM02B-GHS-TB-LF-SN [mm]
  rect 0.6x1.7 smd: 1(-0.625,1.6) 2(0.625,1.6)
  rect 1.3x2.9 smd: 3(2.475,-1.6) 4(-2.475,-1.6)
  silkscreen extent -2.9,-2.7 2.9,1.35
CONN-TH_SM03B-GHS-TB-LF-SN [mm]
  rect 0.6x1.7 smd: 1(-1.25,1.854) 2(0,1.854) 3(1.25,1.854)
  rect 1x2.2 smd: 4(3.1,-1.854) 5(-3.1,-1.854)
  silkscreen extent -3.5,-2.77 3.5,2.06
CONN-TH_SM06B-GHS-TB-LF-SN [mm]
  rect 0.6x1.7 smd: 1(-3.125,1.749) 2(-1.876,1.749) 3(-0.625,1.749) 4(0.625,1.749) 5(1.875,1.749) 6(3.124,1.749)
  rect 1x2.7 smd: 7(-4.975,-1.749) 8(4.975,-1.749)
  silkscreen extent -5.5,-2.75 5.5,1.95
CONN-TH_XH2.54-3P [mm]
  round 1.65 hole 1.1: 1(-2.5,0) 2(0,0) 3(2.5,0)
  silkscreen extent -5,-3.4 5,2.4
DFN1006-2L-BI [mm]
  rect 0.45x0.55 smd: 1(-0.425,0) 2(0.425,0)
  silkscreen extent -0.8,-0.4 0.8,0.4
DFN2020-8_L2.0-W2.0-P0.50-BL-EP [mm]
  rect 0.28x0.5 smd: 1(-0.75,-1) 2(-0.25,-1) 3(0.25,-1) 4(0.75,-1) 5(0.75,1) 6(0.25,1) 7(-0.25,1) 8(-0.75,1)
  rect 1.8x1 smd: 9(0,0)
  silkscreen extent -1.08,-1.59 1.08,1.08
DFN-10_L2.5-W1.0-P0.50-BL-2 [mm]
  rect 0.2x0.675 smd: 1(-1,-0.44) 2(-0.5,-0.44) 4(0.5,-0.44) 5(1,-0.44) 6(0.999,0.44) 7(0.5,0.44) 9(-0.5,0.44) 10(-0.999,0.44)
  rect 0.4x0.675 smd: 3(0,-0.44) 8(0,0.44)
  silkscreen extent -1.4,-1.4 1.4,1.02
DS1095-06-BNR0 [mm]
  round 1.524 hole 0.914: 1(-3.5,0) 2(-1,0) 3(1,0) 4(3.5,0)
  oval 2x3 hole 1.25: 5(-6.4,-0.9) 6(6.4,-0.9) 7(-6,-7.4) 8(6,-7.4)
  silkscreen extent -6.5,-9.5 6.5,1
DS-201 [mm]
  oval 0.8x3.3 hole 0.5 slot 3 at 90 deg: 1(13.8,-4.5)
  oval 0.75x2.8 hole 0.45 slot 2.5 at 90 deg: 2(7.8,-4.5)
  silkscreen extent 0,-9 14.5,0
"EDAC 690-019-298-412" [mm]
  rect 0.3x2.6 smd: 1(4.5,0.73) 2(4,0.73) 3(3.5,0.73) 4(3,0.73) 5(2.5,0.73) 6(2,0.73) 7(1.5,0.73) 8(1,0.73) 9(0.5,0.73) 10(0,0.73) 11(-0.5,0.73) 12(-1,0.73) 13(-1.5,0.73) 14(-2,0.73) 15(-2.5,0.73) 16(-3,0.73) 17(-3.5,0.73) 18(-4,0.73) 19(-4.5,0.73)
  oval 1.5x3.3 hole 0.9 slot 2.7 at 90 deg: SH1(7.25,0) SH2(-7.25,0)
  oval 1.5x2.3 hole 0.9 slot 1.7 at 90 deg: SH3(-7.25,-5.96) SH4(7.25,-5.96)
  silkscreen extent -8.1,-9.55 8.1,2.6
F1206 [mm]
  rect 1.19x1.728 smd: 1(-1.445,0) 2(1.445,0)
  silkscreen extent -2.27,-1.09 2.27,1.09
FILTER-SMD_3P-L1.6-W0.8-L_NFM18CC223R1C3D [mm]
  rect 0.5x1 smd: 1(-0.8,0) 3(0.8,0)
  rect 0.5x0.4 smd: 2(0,-0.4) 2(0,0.4)
  silkscreen extent -1.59,-0.8 1.25,0.8
HDR-F-2.54_2X2 [mil]
  rect 60x60 hole 36: 1(-50,-50)
  round 60 hole 36: 2(-50,50) 3(50,-50) 4(50,50)
  silkscreen extent -100,-100 100,100
HDR-M-2.54_1X1 [mil]
  rect 62x62 hole 35: 1(0,0)
  silkscreen extent -50,-50 50,50
HDR-TH_40P-P2.00-V-F-R2-C20-S2.00 [mm]
  rect 1.3x1.3 hole 0.85: 1(-19,-1)
  round 1.3 hole 0.85: 2(-19,1) 3(-17,-1) 4(-17,1) 5(-15,-1) 6(-15,1) 7(-13,-1) 8(-13,1) 9(-11,-1) 10(-11,1) 11(-9,-1) 12(-9,1) 13(-7,-1) 14(-7,1) 15(-5,-1) 16(-5,1) 17(-3,-1) 18(-3,1) 19(-1,-1) 20(-1,1) 21(1,-1) 22(1,1) 23(3,-1) 24(3,1) 25(5,-1) 26(5,1) 27(7,-1) 28(7,1) 29(9,-1) 30(9,1) 31(11,-1) 32(11,1) 33(13,-1) 34(13,1) 35(15,-1) 36(15,1) 37(17,-1) 38(17,1) 39(19,-1) 40(19,1)
  silkscreen extent -20.3,-2.29 20.24,2.25
IND-SMD_L3.0-W3.0_IHLP-1212BZ [mm]
  rect 1.5x1.2 smd: 1(-1.35,0) 2(1.35,0)
  silkscreen extent -1.5,-1.5 1.5,1.5
IND-SMD_L4.0-W4.0_VLCF4020 [mm]
  rect 1.8x4 smd: 1(-1.6,0) 2(1.6,0)
  silkscreen extent -3.08,-2.25 2.55,2.25
IND-SMD_L5.5-W5.2 [mm]
  rect 1.5x2.5 smd: 1(-2.3,0) 2(2.3,0)
  silkscreen extent -2.8,-2.6 2.8,2.6
IND-SMD_L6.5-W6.5_IHLP-2525 [mm]
  rect 2.42x3.43 smd: 1(-2.925,0) 2(2.925,0)
  silkscreen extent -3.25,-3.25 3.25,3.25
L0603 [mm]
  rect 0.8x0.864 smd: 1(-0.7,0) 2(0.7,0)
  silkscreen extent -1.42,-0.65 1.42,0.65
L-KLS5-CR2032-23-B1 [mm]
  rect 3.2x4.2 smd: 1(-14.65,0) 2(14.65,0)
  silkscreen extent -14.42,-8 14.42,8
LQFP-64_L10.0-W10.0-P0.50-LS12.0-BL [mm]
  oval 0.3x2 smd: 1(-3.75,-5.75) 2(-3.25,-5.75) 3(-2.75,-5.75) 4(-2.25,-5.75) 5(-1.75,-5.75) 6(-1.25,-5.75) 7(-0.75,-5.75) 8(-0.25,-5.75) 9(0.25,-5.75) 10(0.75,-5.75) 11(1.25,-5.75) 12(1.75,-5.75) 13(2.25,-5.75) 14(2.75,-5.75) 15(3.25,-5.75) 16(3.75,-5.75) 33(3.75,5.75) 34(3.25,5.75) 35(2.75,5.75) 36(2.25,5.75) 37(1.75,5.75) 38(1.25,5.75) 39(0.75,5.75) 40(0.25,5.75) 41(-0.25,5.75) 42(-0.75,5.75) 43(-1.25,5.75) 44(-1.75,5.75) 45(-2.25,5.75) 46(-2.75,5.75) 47(-3.25,5.75) 48(-3.75,5.75)
  oval 2x0.3 smd: 17(5.75,-3.75) 18(5.75,-3.25) 19(5.75,-2.75) 20(5.75,-2.25) 21(5.75,-1.75) 22(5.75,-1.25) 23(5.75,-0.75) 24(5.75,-0.25) 25(5.75,0.25) 26(5.75,0.75) 27(5.75,1.25) 28(5.75,1.75) 29(5.75,2.25) 30(5.75,2.75) 31(5.75,3.25) 32(5.75,3.75) 49(-5.75,3.75) 50(-5.75,3.25) 51(-5.75,2.75) 52(-5.75,2.25) 53(-5.75,1.75) 54(-5.75,1.25) 55(-5.75,0.75) 56(-5.75,0.25) 57(-5.75,-0.25) 58(-5.75,-0.75) 59(-5.75,-1.25) 60(-5.75,-1.75) 61(-5.75,-2.25) 62(-5.75,-2.75) 63(-5.75,-3.25) 64(-5.75,-3.75)
  silkscreen extent -5,-5.79 5,5
MICRO-USB-SMD_1981568-1 [mm]
  rect 0.4x1.35 smd: 1(-1.297,1.338) 2(-0.662,1.338) 3(-0.001,1.338) 4(0.659,1.338) 5(1.294,1.338)
  rect 1.45x1.3 smd: 6(-3.425,-1.337) 6(3.425,-1.338)
  rect 1.6x1.4 smd: 6(-3.2,1.113) 6(3.2,1.113)
  rect 1.9x1.9 smd: 6(-1.195,-1.337) 6(1.193,-1.337)
  Board Outline Layer lines w0.254: -4.1,-3.454 -4,-3.454 ; -4.1,-3.454 -4.1,-4.1 -4.1,-3.454 ; -4.1,-3.454 -4,-3.454 ; -4,-3.454 -3.861,-3.454 ; -4,-3.454 -3.861,-3.454 ; -3.861,-3.454 3.81,-3.454 ; -3.861,-3.454 3.81,-3.454 ; 3.81,-3.454 4.064,-3.454 ; 3.81,-3.454 4.064,-3.454 ; 4.064,-3.454 4.064,-4 4.064,-3.454
  silkscreen extent -4.04,-4.07 4.04,1.55
OSC-SMD_3P-L3.2-W1.3-P1.2-L [mm]
  rect 0.65x1.7 smd: 1(-1.2,0) 3(1.2,0)
  rect 0.5x1.7 smd: 2(0,0)
  silkscreen extent -1.75,-0.66 1.75,0.66
OSC-SMD_4P-L3.2-W2.5-BL-1 [mm]
  rect 1.4x1.2 smd: 1(-1.1,-0.8) 2(1.1,-0.8) 3(1.1,0.8) 4(-1.1,0.8)
  silkscreen extent -1.27,-1.9 0.17,1.25
PCI-SMD_APCI0164-P001A [mm]
  rect 0.3x1.55 smd: 1(-9.25,3.225) 2(-9,-3.225) 3(-8.75,3.225) 4(-8.5,-3.225) 5(-8.25,3.225) 6(-8,-3.225) 7(-7.75,3.225) 8(-7.5,-3.225) 9(-7.25,3.225) 10(-7,-3.225) 11(-6.75,3.225) 12(-6.5,-3.225) 13(-6.25,3.225) 14(-6,-3.225) 15(-5.75,3.225) 16(-5.5,-3.225) 17(-5.25,3.225) 18(-5,-3.225) 19(-4.75,3.225) 20(-4.5,-3.225) 21(-4.25,3.225) 22(-4,-3.225) 23(-3.75,3.225) 24(-3.5,-3.225) 25(-3.25,3.225) 26(-3,-3.225) 27(-2.75,3.225) 28(-2.5,-3.225) 29(-2.25,3.225) 30(-2,-3.225) 31(-1.75,3.225) 32(-1.5,-3.225) 33(-1.25,3.225) 34(-1,-3.225) 35(-0.75,3.225) 36(-0.5,-3.225) 37(-0.25,3.225) 38(0,-3.225) 39(0.25,3.225) 40(0.5,-3.225) 41(0.75,3.225) 42(1,-3.225) 43(1.25,3.225) 44(1.5,-3.225) 45(1.75,3.225) 46(2,-3.225) 47(2.25,3.225) 48(2.5,-3.225) 49(2.75,3.225) 50(3,-3.225) 51(3.25,3.225) 52(3.5,-3.225) 53(3.75,3.225) 54(4,-3.225) 55(4.25,3.225) 56(4.5,-3.225) 57(4.75,3.225) 58(5,-3.225) 67(7.25,3.225) 68(7.5,-3.225) 69(7.75,3.225) 70(8,-3.225) 71(8.25,3.225) 72(8.5,-3.225) 73(8.75,3.225) 74(9,-3.225) 75(9.25,3.225)
  rect 1.2x2.75 smd: 76(-10.35,3) 76(10.35,3)
  Board Outline Layer circle w0.005: c-10,-1.5 r0.55
  Board Outline Layer circle w0.005: c10,-1.5 r0.8
  Board Outline Layer region: -9.45,-1.5 -9.505,-1.739 -9.657,-1.93 -9.878,-2.036 -10.122,-2.036 -10.343,-1.93 -10.496,-1.739 -10.55,-1.5 -10.55,-1.5 -10.496,-1.261 -10.343,-1.07 -10.122,-0.964 -9.878,-0.964 -9.657,-1.07 -9.505,-1.261 -9.45,-1.5
  Board Outline Layer region: 10.8,-1.5 10.721,-1.847 10.499,-2.126 10.178,-2.28 9.822,-2.28 9.501,-2.126 9.279,-1.847 9.2,-1.5 9.2,-1.5 9.279,-1.153 9.501,-0.875 9.822,-0.72 10.178,-0.72 10.499,-0.875 10.721,-1.153 10.8,-1.5
  Multi-Layer board cut-out: -9.45,-1.5 -9.505,-1.739 -9.657,-1.93 -9.878,-2.036 -10.122,-2.036 -10.343,-1.93 -10.496,-1.739 -10.55,-1.5 -10.55,-1.5 -10.496,-1.261 -10.343,-1.07 -10.122,-0.964 -9.878,-0.964 -9.657,-1.07 -9.505,-1.261 -9.45,-1.5
  Multi-Layer board cut-out: 10.8,-1.5 10.721,-1.847 10.499,-2.126 10.178,-2.28 9.822,-2.28 9.501,-2.126 9.279,-1.847 9.2,-1.5 9.2,-1.5 9.279,-1.153 9.501,-0.875 9.822,-0.72 10.178,-0.72 10.499,-0.875 10.721,-1.153 10.8,-1.5
  silkscreen extent -10.92,-3.94 10.92,4.76
QFN-30_L5.0-W4.0-P0.50-TL_MP2762A [mm]
  rect 1.3x0.25 smd: 1(-1.4,1.5) 4(-1.4,0) 7(-1.4,-1.5)
  rect 0.8x0.25 smd: 2(-1.65,1) 3(-1.65,0.5) 5(-1.65,-0.5) 6(-1.65,-1)
  rect 0.2x0.8 smd: 8(-1.15,-2.4) 9(-0.75,-2.4) 10(-0.35,-2.4) 11(0.05,-2.4) 12(0.45,-2.4) 13(0.85,-2.4) 14(1.25,-2.4) 15(1.65,-2.4) 23(1.65,2.4) 24(1.25,2.4) 25(0.85,2.4) 26(0.45,2.4) 27(0.05,2.4) 28(-0.35,2.4) 29(-0.75,2.4) 30(-1.15,2.4)
  rect 2.3x0.25 smd: 16(1.4,-1.5) 17(1.4,-1) 18(1.4,-0.5) 19(1.4,0) 20(1.4,0.5) 21(1.4,1) 22(1.4,1.5)
  silkscreen extent -2.48,-2.68 2.42,2.68
R0402 [mm]
  rect 0.566x0.54 smd: 1(-0.433,0) 2(0.433,0)
  silkscreen extent -0.94,-0.5 0.94,0.5
R0603 [mil]
  rect 31.75x34.02 smd: 1(-29.66,0) 2(29.66,0)
  silkscreen extent -55,-26 55,26
R1206 [mil]
  rect 47.54x66.97 smd: 1(-58.22,0) 2(58.22,0)
  silkscreen extent -91,-42 91,42
RJ45-TH_LPJG0926HENL_C22457393 [mil]
  round 60 hole 35.43: 1(-225,254.93) 2(-175,154.93) 3(-125,254.93) 4(-75,154.93) 5(-25,254.93) 6(25,154.93) 7(75,254.93) 8(125,154.93) 9(175,254.93) 10(225,154.93) 11(-225,55.71) 12(-125,5.71) 13(125,5.71) 14(225,55.71)
  round 62.99 hole 40.16: 15(-261.02,-254.92) 16(-161.02,-254.92) 17(161.02,-254.92) 18(261.02,-254.92)
  round 90.55 hole 66.93: S1(-310.04,25) S2(310.04,25)
  Board Outline Layer circle w1: c224.99,-95.08 r62.99
  Board Outline Layer circle w1: c-225.01,-95.08 r62.99
  Board Outline Layer region: 287.99,-95.08 281.75,-122.41 264.27,-144.33 239.01,-156.49 210.98,-156.49 185.72,-144.33 168.24,-122.41 162,-95.08 162,-95.08 168.24,-67.75 185.72,-45.83 210.98,-33.67 239.01,-33.67 264.27,-45.83 281.75,-67.75 287.99,-95.08
  Board Outline Layer region: -162.01,-95.08 -168.25,-122.41 -185.73,-144.33 -210.99,-156.49 -239.02,-156.49 -264.28,-144.33 -281.76,-122.41 -288,-95.08 -288,-95.08 -281.76,-67.75 -264.28,-45.83 -239.02,-33.67 -210.99,-33.67 -185.73,-45.83 -168.25,-67.75 -162.01,-95.08
  Multi-Layer board cut-out: 287.99,-95.08 281.75,-122.41 264.27,-144.33 239.01,-156.49 210.98,-156.49 185.72,-144.33 168.24,-122.41 162,-95.08 162,-95.08 168.24,-67.75 185.72,-45.83 210.98,-33.67 239.01,-33.67 264.27,-45.83 281.75,-67.75 287.99,-95.08
  Multi-Layer board cut-out: -162.01,-95.08 -168.25,-122.41 -185.73,-144.33 -210.99,-156.49 -239.02,-156.49 -264.28,-144.33 -281.76,-122.41 -288,-95.08 -288,-95.08 -281.76,-67.75 -264.28,-45.83 -239.02,-33.67 -210.99,-33.67 -185.73,-45.83 -168.25,-67.75 -162.01,-95.08
  silkscreen extent -314,-520 314,316
SC-88A_L2.0-W1.3-P0.65-LS2.1-BL [mm]
  rect 0.399x0.8 smd: 1(-0.65,-1.067) 2(0,-1.067) 3(0.65,-1.067) 4(0.65,1.067) 5(-0.65,1.066)
  silkscreen extent -1.27,-0.94 0.99,0.41
SENSOR-SMD_L1.6-W0.8-XL-1608PDC [mm]
  rect 0.8x0.8 smd: 1(-0.8,0) 2(0.8,0)
  silkscreen extent -1.82,-0.86 1.77,0.86
SOD-123_L2.7-W1.6-LS3.7-RD [mm]
  rect 0.91x1.22 smd: 1(-1.635,0) 2(1.635,0)
  silkscreen extent -1.6,-1 1.38,1
SOD-323_L1.8-W1.3-LS2.5-RD [mm]
  rect 1x0.75 smd: 1(-1.173,0) 2(1.173,0)
  silkscreen extent -1.08,-0.8 0.9,0.8
SOP-8_L4.9-W3.9-P1.27-LS6.0-BL-EP-2 [mm]
  oval 0.63x1.865 smd: 1(-1.905,-2.682) 2(-0.635,-2.682) 3(0.635,-2.682) 4(1.905,-2.682) 5(1.905,2.682) 6(0.635,2.682) 7(-0.635,2.682) 8(-1.905,2.682)
  rect 3.3x2.4 smd: 9(0,0)
  silkscreen extent -2.82,-2.83 2.58,1.52
SOT-23-3_L2.9-W1.3-P1.90-LS2.4-BR [mm]
  rect 1.25x0.7 smd: 1(1,-0.95) 2(1,0.95) 3(-1,0)
  silkscreen extent -0.73,-1.53 0.73,1.53
SOT-23-3_L2.9-W1.4-P1.90-LS2.5-BR [mm]
  rect 1.07x0.6 smd: 1(1.035,-0.95) 2(1.035,0.95) 3(-1.035,0)
  silkscreen extent -0.76,-1.52 0.76,1.52
SOT-23-3_L2.9-W1.6-P1.90-LS2.8-BR [mm]
  rect 1.07x0.6 smd: 1(1.235,-0.95) 2(1.235,0.95) 3(-1.235,0)
  silkscreen extent -0.88,-1.54 0.88,1.54
SOT-23-6_L2.9-W1.6-P0.95-LS2.8-BL [mil]
  rect 20.95x42.2 smd: 1(-37.4,-45.24) 2(0,-45.24) 3(37.4,-45.24) 4(37.4,45.24) 5(0,45.24) 6(-37.4,45.24)
  silkscreen extent -72,-57 61,35
SOT-23-6_L2.9-W1.6-P0.95-LS2.8-BR [mm]
  rect 1.1x0.6 smd: 1(1.35,-0.95) 2(1.35,0) 3(1.35,0.95) 4(-1.35,0.95) 5(-1.35,0) 6(-1.35,-0.95)
  silkscreen extent -0.9,-1.78 1.52,1.55
SW-TH_10P-P2.54_DS1040-05RN [mm]
  round 1.5 hole 1: 1(-5.08,-3.81) 2(-2.54,-3.81) 3(0,-3.81) 4(2.54,-3.81) 5(5.08,-3.81) 6(5.08,3.81) 7(2.54,3.81) 8(0,3.81) 9(-2.54,3.81) 10(-5.08,3.81)
  silkscreen extent -7.08,-4.95 7.11,4.95
TF-SMD_DM3CS-SF [mm]
  rect 0.7x2 smd: 1(3.125,-6.35) 2(2.025,-6.35) 3(0.925,-6.35) 4(-0.177,-6.35) 5(-1.275,-6.35) 6(-2.375,-6.35) 7(-3.475,-6.35) 8(-4.575,-6.35)
  rect 2.7x1.4 smd: 9(1.724,6.35) 12(-3.176,6.35)
  rect 1.7x2.6 smd: 10(6.674,-5.851)
  rect 1x2.6 smd: 11(-6.674,-5.851)
  rect 1.2x1.2 smd: 13(4.775,6.35)
  silkscreen extent -6.99,-7.49 6.99,7.24
TSOT-23-5_L2.9-W1.6-P0.95-LS2.8-BR [mm]
  rect 1.1x0.7 smd: 1(1.294,-0.951) 2(1.294,-0.001) 3(1.294,0.951) 4(-1.294,0.951) 5(-1.294,-0.949)
  silkscreen extent -0.97,-1.65 1.52,1.61
USB-A-TH_H181-AF2R06-12ALCR [mm]
  round 1.1 hole 0.7: 1(-3.5,-1.35) 2(-1,-1.35) 3(1,-1.35) 4(3.5,-1.35) 5(4,0.15) 6(2,0.15) 7(0,0.15) 8(-2,0.15) 9(-4,0.15) 10(-3.5,1.85) 11(-1,1.85) 12(1,1.85) 13(3.5,1.85) 14(4,3.35) 15(2,3.35) 16(0,3.35) 17(-2,3.35) 18(-4,3.35)
  round 3 hole 2.3 copper offset 0,0: 19(-6.57,2.33) 20(6.57,2.33)
  round 3 hole 2.3: 19(-6.57,-3.35) 20(6.57,-3.35)
  silkscreen extent -6.6,-12.57 6.6,4.7
USB-C-SMD_TYPE-C16PIN-SHOUHAN [mm]
  oval 1x2.1 hole 0.6 slot 1.7 at 90 deg: 1(-4.32,1.63) 2(4.32,1.63)
  oval 1x1.8 hole 0.6 slot 1.4 at 90 deg: 3(-4.32,-2.55) 4(4.32,-2.55)
  rect 0.55x1.45 smd: A1B12(-3.2,2.55) A4B9(-2.4,2.55) B1A12(3.2,2.55) B4A9(2.4,2.55)
  rect 0.3x1.45 smd: A5(-1.25,2.55) A6(-0.25,2.55) A7(0.25,2.55) A8(1.25,2.55) B5(1.75,2.55) B6(0.75,2.55) B7(-0.75,2.55) B8(-1.75,2.55)
  Board Outline Layer circle w0.005: c-2.89,1.1 r0.325
  Board Outline Layer circle w0.005: c2.89,1.1 r0.325
  Board Outline Layer region: -2.565,1.1 -2.597,0.959 -2.687,0.846 -2.818,0.783 -2.962,0.783 -3.093,0.846 -3.183,0.959 -3.215,1.1 -3.215,1.1 -3.183,1.241 -3.093,1.354 -2.962,1.417 -2.818,1.417 -2.687,1.354 -2.597,1.241 -2.565,1.1
  Board Outline Layer region: 3.215,1.1 3.183,0.959 3.093,0.846 2.962,0.783 2.818,0.783 2.687,0.846 2.597,0.959 2.565,1.1 2.565,1.1 2.597,1.241 2.687,1.354 2.818,1.417 2.962,1.417 3.093,1.354 3.183,1.241 3.215,1.1
  Multi-Layer board cut-out: -2.565,1.1 -2.597,0.959 -2.687,0.846 -2.818,0.783 -2.962,0.783 -3.093,0.846 -3.183,0.959 -3.215,1.1 -3.215,1.1 -3.183,1.241 -3.093,1.354 -2.962,1.417 -2.818,1.417 -2.687,1.354 -2.597,1.241 -2.565,1.1
  Multi-Layer board cut-out: 3.215,1.1 3.183,0.959 3.093,0.846 2.962,0.783 2.818,0.783 2.687,0.846 2.597,0.959 2.565,1.1 2.565,1.1 2.597,1.241 2.687,1.354 2.818,1.417 2.962,1.417 3.093,1.354 3.183,1.241 3.215,1.1
  silkscreen extent -4.45,-5.15 4.45,0.36
USON-10_L2.5-W1.0-P0.50-BL [mm]
  rect 0.25x0.609 smd: 1(-1,-0.415) 2(-0.5,-0.415) 4(0.5,-0.415) 5(1,-0.415) 6(1,0.415) 7(0.5,0.415) 9(-0.5,0.415) 10(-1,0.415)
  rect 0.38x0.609 smd: 3(0,-0.415) 8(0,0.415)
  silkscreen extent -1.33,-1.12 1.33,0.58
VQFN-20_L4.6-W3.6-P0.50-BL [mm]
  rect 0.7x0.244 smd: 1(-2.185,-0.75) 10(2.185,-0.75) 11(2.185,0.75) 20(-2.185,0.75)
  rect 0.244x0.7 smd: 2(-1.748,-1.727) 3(-1.248,-1.727) 4(-0.748,-1.727) 5(-0.248,-1.727) 6(0.252,-1.727) 7(0.752,-1.727) 8(1.252,-1.727) 9(1.752,-1.727) 12(1.752,1.727) 13(1.252,1.727) 14(0.752,1.727) 15(0.252,1.727) 16(-0.248,1.727) 17(-0.748,1.727) 18(-1.248,1.727) 19(-1.748,1.727)
  round 0.406 smd: 21(0,0.001)
  Top Layer region: -1.621,0.143 -2.485,0.146 -2.485,0.376 -1.621,0.38 -1.618,0.565 -1.522,0.566 -1.521,1.016 1.526,1.016 1.523,0.571 1.621,0.571 1.624,0.381 2.485,0.381 2.485,0.147 1.621,0.147 1.624,-0.137 2.485,-0.137 2.485,-0.371 1.621,-0.371 1.624,-0.561 1.526,-0.561 1.526,-1.014 -1.522,-1.016 -1.522,-0.567 -1.62,-0.567 -1.619,-0.374 -2.481,-0.374 -2.48,-0.143 -1.618,-0.144 -1.619,0.145
  silkscreen extent -2.8,-1.8 2.3,1.8
WSON-10_L3.0-W2.0-P0.50-BL-EP [mm]
  rect 0.28x0.505 smd: 1(-1,-0.928) 2(-0.5,-0.928) 3(0,-0.928) 4(0.5,-0.928) 5(1,-0.928) 6(1,0.928) 7(0.5,0.928) 8(0,0.928) 9(-0.5,0.928) 10(-1,0.928)
  rect 2.4x0.84 smd: 11(0,0)
  silkscreen extent -1.58,-1.58 1.58,1.08

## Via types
v1: diameter 15.75, hole 7.87, Top Layer to Bottom Layer, 8 vias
